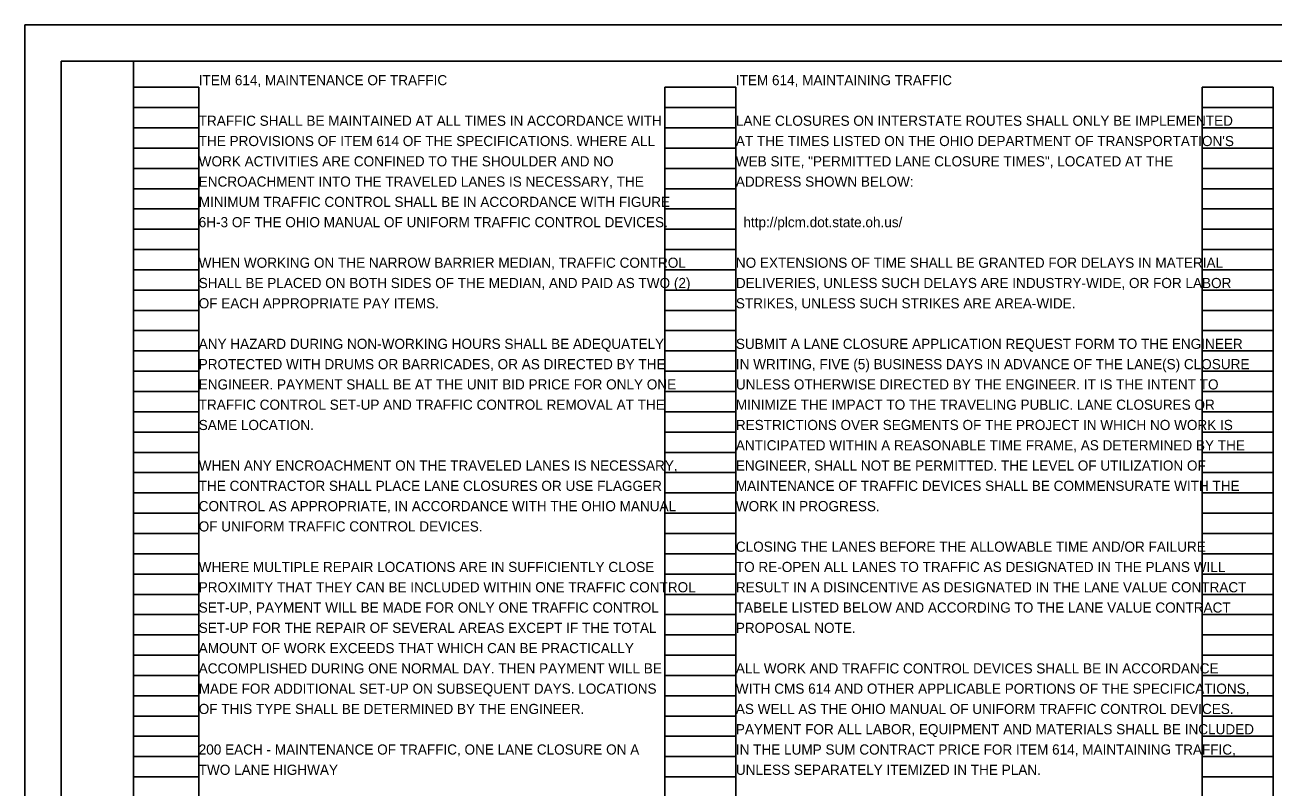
# Model space of a CAD drawing. Extents: x 0 to 34, y 0 to 22.
# Drawn here: x 0 to 17.24, y 11.48 to 22 of the extents above; entities that cross this region are included whole.
import ezdxf

# ---------------------------------------------------------------- set-up
doc = ezdxf.new("R2010")
doc.units = 0
for name, color, linetype in [('SH_Border', 7, 'Continuous'), ('SH_Cut_Line', 7, 'Continuous'), ('SH_Data', 7, 'Continuous'), ('SH_Text', 7, 'Continuous')]:
    doc.layers.add(name, color=color, linetype=linetype)

msp = doc.modelspace()

# ---------------------------------------------------------------- linework, layer by layer
at = {"layer": 'SH_Border'}
for points in [[(0.5, 21.5), (1.5, 21.5), (1.5, 0.5), (0.5, 0.5)], [(1.5, 21.5), (33.5, 21.5), (33.5, 0.5), (1.5, 0.5)]]:
    msp.add_lwpolyline(points, close=True, dxfattribs=at)
at = {"layer": 'SH_Cut_Line'}
msp.add_lwpolyline([(0, 0), (34, 0), (34, 22), (0, 22)], close=True, dxfattribs=at)
at = {"layer": 'SH_Data'}
for p, q in [((1.5, 0.98), (1.5, 21.14)), ((1.5, 21.14), (2.4, 21.14)), ((2.4, 0.98), (2.4, 21.14)), ((8.84, 0.98), (8.84, 21.14)), ((8.84, 21.14), (9.82, 21.14)), ((9.82, 0.98), (9.82, 21.14)), ((16.26, 0.98), (16.26, 21.14)), ((16.26, 21.14), (17.24, 21.14)), ((17.24, 0.98), (17.24, 21.14)), ((1.5, 20.86), (2.4, 20.86)), ((8.84, 20.86), (9.82, 20.86)), ((16.26, 20.86), (17.24, 20.86)), ((1.5, 20.58), (2.4, 20.58)), ((8.84, 20.58), (9.82, 20.58)), ((16.26, 20.58), (17.24, 20.58)), ((1.5, 20.3), (2.4, 20.3)), ((8.84, 20.3), (9.82, 20.3)), ((16.26, 20.3), (17.24, 20.3)), ((1.5, 20.02), (2.4, 20.02)), ((8.84, 20.02), (9.82, 20.02)), ((16.26, 20.02), (17.24, 20.02)), ((1.5, 19.74), (2.4, 19.74)), ((8.84, 19.74), (9.82, 19.74)), ((16.26, 19.74), (17.24, 19.74)), ((1.5, 19.46), (2.4, 19.46)), ((8.84, 19.46), (9.82, 19.46)), ((16.26, 19.46), (17.24, 19.46)), ((1.5, 19.18), (2.4, 19.18)), ((8.84, 19.18), (9.82, 19.18)), ((16.26, 19.18), (17.24, 19.18)), ((1.5, 18.9), (2.4, 18.9)), ((8.84, 18.9), (9.82, 18.9)), ((16.26, 18.9), (17.24, 18.9)), ((1.5, 18.62), (2.4, 18.62)), ((8.84, 18.62), (9.82, 18.62)), ((16.26, 18.62), (17.24, 18.62)), ((1.5, 18.34), (2.4, 18.34)), ((8.84, 18.34), (9.82, 18.34)), ((16.26, 18.34), (17.24, 18.34)), ((1.5, 18.06), (2.4, 18.06)), ((8.84, 18.06), (9.82, 18.06)), ((16.26, 18.06), (17.24, 18.06)), ((1.5, 17.78), (2.4, 17.78)), ((8.84, 17.78), (9.82, 17.78)), ((16.26, 17.78), (17.24, 17.78)), ((1.5, 17.5), (2.4, 17.5)), ((8.84, 17.5), (9.82, 17.5)), ((16.26, 17.5), (17.24, 17.5)), ((1.5, 17.22), (2.4, 17.22)), ((8.84, 17.22), (9.82, 17.22)), ((16.26, 17.22), (17.24, 17.22)), ((1.5, 16.94), (2.4, 16.94)), ((8.84, 16.94), (9.82, 16.94)), ((16.26, 16.94), (17.24, 16.94)), ((1.5, 16.66), (2.4, 16.66)), ((8.84, 16.66), (9.82, 16.66)), ((16.26, 16.66), (17.24, 16.66)), ((1.5, 16.38), (2.4, 16.38)), ((8.84, 16.38), (9.82, 16.38)), ((16.26, 16.38), (17.24, 16.38)), ((1.5, 16.1), (2.4, 16.1)), ((8.84, 16.1), (9.82, 16.1)), ((16.26, 16.1), (17.24, 16.1)), ((1.5, 15.82), (2.4, 15.82)), ((8.84, 15.82), (9.82, 15.82)), ((16.26, 15.82), (17.24, 15.82)), ((1.5, 15.54), (2.4, 15.54)), ((8.84, 15.54), (9.82, 15.54)), ((16.26, 15.54), (17.24, 15.54)), ((1.5, 15.26), (2.4, 15.26)), ((8.84, 15.26), (9.82, 15.26)), ((16.26, 15.26), (17.24, 15.26)), ((1.5, 14.98), (2.4, 14.98)), ((8.84, 14.98), (9.82, 14.98)), ((16.26, 14.98), (17.24, 14.98)), ((1.5, 14.7), (2.4, 14.7)), ((8.84, 14.7), (9.82, 14.7)), ((16.26, 14.7), (17.24, 14.7)), ((1.5, 14.42), (2.4, 14.42)), ((8.84, 14.42), (9.82, 14.42)), ((16.26, 14.42), (17.24, 14.42)), ((1.5, 14.14), (2.4, 14.14)), ((8.84, 14.14), (9.82, 14.14)), ((16.26, 14.14), (17.24, 14.14)), ((1.5, 13.86), (2.4, 13.86)), ((8.84, 13.86), (9.82, 13.86)), ((16.26, 13.86), (17.24, 13.86)), ((1.5, 13.58), (2.4, 13.58)), ((8.84, 13.58), (9.82, 13.58)), ((16.26, 13.58), (17.24, 13.58)), ((1.5, 13.3), (2.4, 13.3)), ((8.84, 13.3), (9.82, 13.3)), ((16.26, 13.3), (17.24, 13.3)), ((1.5, 13.02), (2.4, 13.02)), ((8.84, 13.02), (9.82, 13.02)), ((16.26, 13.02), (17.24, 13.02)), ((1.5, 12.74), (2.4, 12.74)), ((8.84, 12.74), (9.82, 12.74)), ((16.26, 12.74), (17.24, 12.74)), ((1.5, 12.46), (2.4, 12.46)), ((8.84, 12.46), (9.82, 12.46)), ((16.26, 12.46), (17.24, 12.46)), ((1.5, 12.18), (2.4, 12.18)), ((8.84, 12.18), (9.82, 12.18)), ((16.26, 12.18), (17.24, 12.18)), ((1.5, 11.9), (2.4, 11.9)), ((8.84, 11.9), (9.82, 11.9)), ((16.26, 11.9), (17.24, 11.9)), ((1.5, 11.62), (2.4, 11.62)), ((8.84, 11.62), (9.82, 11.62)), ((16.26, 11.62), (17.24, 11.62))]:
    msp.add_line(p, q, dxfattribs=at)

# ---------------------------------------------------------------- texts
at = {"layer": 'SH_Text'}
for s, p in [('ITEM 614, MAINTENANCE OF TRAFFIC', (2.4, 21.168)), ('ITEM 614, MAINTAINING TRAFFIC', (9.82, 21.168)), ('TRAFFIC SHALL BE MAINTAINED AT ALL TIMES IN ACCORDANCE WITH', (2.4, 20.608)), ('LANE CLOSURES ON INTERSTATE ROUTES SHALL ONLY BE IMPLEMENTED', (9.82, 20.608)), ('THE PROVISIONS OF ITEM 614 OF THE SPECIFICATIONS. WHERE ALL', (2.4, 20.328)), ("AT THE TIMES LISTED ON THE OHIO DEPARTMENT OF TRANSPORTATION'S", (9.82, 20.328)), ('WORK ACTIVITIES ARE CONFINED TO THE SHOULDER AND NO', (2.4, 20.048)), ('WEB SITE, "PERMITTED LANE CLOSURE TIMES", LOCATED AT THE', (9.82, 20.048)), ('ENCROACHMENT INTO THE TRAVELED LANES IS NECESSARY, THE', (2.4, 19.768)), ('ADDRESS SHOWN BELOW:', (9.82, 19.768)), ('MINIMUM TRAFFIC CONTROL SHALL BE IN ACCORDANCE WITH FIGURE', (2.4, 19.488)), ('6H-3 OF THE OHIO MANUAL OF UNIFORM TRAFFIC CONTROL DEVICES.', (2.4, 19.208)), ('  http://plcm.dot.state.oh.us/  ', (9.82, 19.208)), ('WHEN WORKING ON THE NARROW BARRIER MEDIAN, TRAFFIC CONTROL', (2.4, 18.648)), ('NO EXTENSIONS OF TIME SHALL BE GRANTED FOR DELAYS IN MATERIAL', (9.82, 18.648)), ('SHALL BE PLACED ON BOTH SIDES OF THE MEDIAN, AND PAID AS TWO (2)', (2.4, 18.368)), ('DELIVERIES, UNLESS SUCH DELAYS ARE INDUSTRY-WIDE, OR FOR LABOR', (9.82, 18.368)), ('OF EACH APPROPRIATE PAY ITEMS.', (2.4, 18.088)), ('STRIKES, UNLESS SUCH STRIKES ARE AREA-WIDE.  ', (9.82, 18.088)), ('ANY HAZARD DURING NON-WORKING HOURS SHALL BE ADEQUATELY', (2.4, 17.528)), ('SUBMIT A LANE CLOSURE APPLICATION REQUEST FORM TO THE ENGINEER', (9.82, 17.528)), ('PROTECTED WITH DRUMS OR BARRICADES, OR AS DIRECTED BY THE', (2.4, 17.248)), ('IN WRITING, FIVE (5) BUSINESS DAYS IN ADVANCE OF THE LANE(S) CLOSURE', (9.82, 17.248)), ('ENGINEER. PAYMENT SHALL BE AT THE UNIT BID PRICE FOR ONLY ONE', (2.4, 16.968)), ('UNLESS OTHERWISE DIRECTED BY THE ENGINEER. IT IS THE INTENT TO', (9.82, 16.968)), ('TRAFFIC CONTROL SET-UP AND TRAFFIC CONTROL REMOVAL AT THE', (2.4, 16.688)), ('MINIMIZE THE IMPACT TO THE TRAVELING PUBLIC. LANE CLOSURES OR', (9.82, 16.688)), ('SAME LOCATION.', (2.4, 16.408)), ('RESTRICTIONS OVER SEGMENTS OF THE PROJECT IN WHICH NO WORK IS', (9.82, 16.408)), ('ANTICIPATED WITHIN A REASONABLE TIME FRAME, AS DETERMINED BY THE', (9.82, 16.128)), ('WHEN ANY ENCROACHMENT ON THE TRAVELED LANES IS NECESSARY, ', (2.4, 15.848)), ('ENGINEER, SHALL NOT BE PERMITTED. THE LEVEL OF UTILIZATION OF', (9.82, 15.848)), ('THE CONTRACTOR SHALL PLACE LANE CLOSURES OR USE FLAGGER', (2.4, 15.568)), ('MAINTENANCE OF TRAFFIC DEVICES SHALL BE COMMENSURATE WITH THE', (9.82, 15.568)), ('CONTROL AS APPROPRIATE, IN ACCORDANCE WITH THE OHIO MANUAL', (2.4, 15.288)), ('WORK IN PROGRESS.', (9.82, 15.288)), ('OF UNIFORM TRAFFIC CONTROL DEVICES.', (2.4, 15.008)), ('CLOSING THE LANES BEFORE THE ALLOWABLE TIME AND/OR FAILURE', (9.82, 14.728)), ('WHERE MULTIPLE REPAIR LOCATIONS ARE IN SUFFICIENTLY CLOSE', (2.4, 14.448)), ('TO RE-OPEN ALL LANES TO TRAFFIC AS DESIGNATED IN THE PLANS WILL', (9.82, 14.448)), ('PROXIMITY THAT THEY CAN BE INCLUDED WITHIN ONE TRAFFIC CONTROL', (2.4, 14.168)), ('RESULT IN A DISINCENTIVE AS DESIGNATED IN THE LANE VALUE CONTRACT', (9.82, 14.168)), ('SET-UP, PAYMENT WILL BE MADE FOR ONLY ONE TRAFFIC CONTROL', (2.4, 13.888)), ('TABELE LISTED BELOW AND ACCORDING TO THE LANE VALUE CONTRACT ', (9.82, 13.888)), ('SET-UP FOR THE REPAIR OF SEVERAL AREAS EXCEPT IF THE TOTAL', (2.4, 13.608)), ('PROPOSAL NOTE.', (9.82, 13.608)), ('AMOUNT OF WORK EXCEEDS THAT WHICH CAN BE PRACTICALLY', (2.4, 13.328)), ('ACCOMPLISHED DURING ONE NORMAL DAY. THEN PAYMENT WILL BE', (2.4, 13.048)), ('ALL WORK AND TRAFFIC CONTROL DEVICES SHALL BE IN ACCORDANCE', (9.82, 13.048)), ('MADE FOR ADDITIONAL SET-UP ON SUBSEQUENT DAYS. LOCATIONS', (2.4, 12.768)), ('WITH CMS 614 AND OTHER APPLICABLE PORTIONS OF THE SPECIFICATIONS,', (9.82, 12.768)), ('OF THIS TYPE SHALL BE DETERMINED BY THE ENGINEER.', (2.4, 12.488)), ('AS WELL AS THE OHIO MANUAL OF UNIFORM TRAFFIC CONTROL DEVICES.', (9.82, 12.488)), ('PAYMENT FOR ALL LABOR, EQUIPMENT AND MATERIALS SHALL BE INCLUDED', (9.82, 12.208)), ('200 EACH - MAINTENANCE OF TRAFFIC, ONE LANE CLOSURE ON A', (2.4, 11.928)), ('IN THE LUMP SUM CONTRACT PRICE FOR ITEM 614, MAINTAINING TRAFFIC,', (9.82, 11.928)), ('TWO LANE HIGHWAY  ', (2.4, 11.648)), ('UNLESS SEPARATELY ITEMIZED IN THE PLAN.', (9.82, 11.648))]:
    msp.add_text(s, height=0.14, dxfattribs=at).set_placement(p)

doc.saveas('drawing.dxf')
